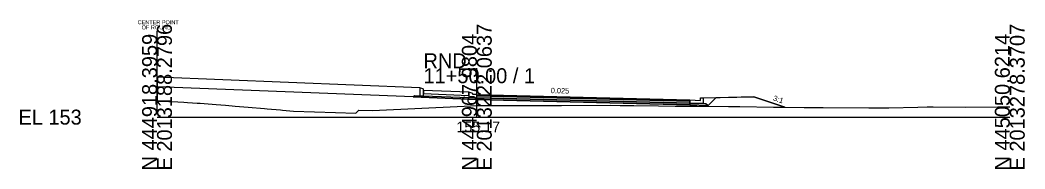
# Model space of a CAD drawing. Extents: x -26 to 163, y -10 to 7518.
# Drawn here: x -25.7 to 162.8, y 2990.3 to 3018.2 of the extents above; entities that cross this region are included whole.
import ezdxf

# ---------------------------------------------------------------- set-up
doc = ezdxf.new("R2010")
doc.units = 0
for name, color, linetype in [('Exist Cross Section Cell', 7, 'Continuous'), ('Exist XS Center Line Elevation Label', 7, 'Continuous'), ('Exist XS Ground Line', 7, 'Continuous'), ('Prop CMT Conc Surface', 7, 'Continuous'), ('Prop CMT Concrete Structures', 7, 'Continuous'), ('Prop CMT Pvmt Course 1', 7, 'Continuous'), ('Prop CMT Pvmt Course 1 CG', 7, 'Continuous'), ('Prop CMT Pvmt Course 2', 7, 'Continuous'), ('Prop CMT Pvmt Course 3', 7, 'Continuous'), ('Prop CMT Pvmt Surface', 7, 'Continuous'), ('Prop CMT Shear Line', 7, 'Continuous'), ('Prop CMT Shear Line Text', 7, 'Continuous'), ('Prop CMT Slope Grass', 7, 'Continuous'), ('Prop CMT Subgrade Earthwork', 7, 'Continuous'), ('Prop XS Earthwork Shape', 7, 'Continuous'), ('Prop XS SE Text', 7, 'Continuous'), ('Prop XS Side Slope Text', 7, 'Continuous')]:
    doc.layers.add(name, color=color, linetype=linetype)

msp = doc.modelspace()

# ---------------------------------------------------------------- linework, layer by layer
at = {"layer": 'Exist Cross Section Cell'}
for p, q in [((60, 3000), (60, 3009.16)), ((0, 3000), (60, 3000)), ((60, 3000), (160, 3000))]:
    msp.add_line(p, q, dxfattribs=at)
at = {"layer": 'Exist XS Ground Line'}
msp.add_lwpolyline([(0, 3003.05), (0.31, 3003.04), (2.2, 3002.95), (3.9, 3002.85), (5.06, 3002.79), (5.69, 3002.75), (6.63, 3002.69), (7.5, 3002.64), (8.08, 3002.6), (11.08, 3002.36), (12.87, 3002.22), (14.1, 3002.13), (14.67, 3002.08), (15.5, 3002.02), (17.12, 3001.89), (20.16, 3001.62), (20.65, 3001.58), (23.19, 3001.35), (23.53, 3001.32), (25.62, 3001.1), (33.49, 3000.87), (37.33, 3000.73), (37.84, 3001.3), (40.43, 3001.26), (57.62, 3002.07), (60, 3002.17), (60.93, 3002.21), (71.71, 3002.2), (73.03, 3002.2), (75.86, 3002.21), (85.13, 3002.22), (86.89, 3002.2), (89.47, 3002.17), (94.09, 3002.09), (97.23, 3002.07), (101.29, 3002.06), (107.23, 3002), (109.34, 3001.97), (115.68, 3001.84), (121.44, 3001.83), (124.99, 3001.79), (133.54, 3001.72), (137.28, 3001.73), (142.76, 3001.89), (144.47, 3001.91), (145.64, 3001.92), (151.67, 3001.86), (157.74, 3001.9), (158.87, 3001.9), (160, 3001.9)], dxfattribs=at)
at = {"layer": 'Prop CMT Conc Surface'}
for points in [[(50, 3005.18), (49.96, 3005.28), (49.85, 3005.33), (49.34, 3005.52)], [(50, 3005.02), (50, 3005.18)], [(60, 3004.22), (59.25, 3004.24), (59.25, 3004.41), (58.5, 3004.66)], [(101.98, 3003.09), (101.98, 3003.59), (102.48, 3003.59)], [(99.99, 3003.22), (101.98, 3003.09)]]:
    msp.add_lwpolyline(points, dxfattribs=at)
at = {"layer": 'Prop CMT Concrete Structures'}
for points in [[(50, 3005.18), (49.96, 3005.28), (49.85, 3005.33), (49.34, 3005.52)], [(49.34, 3005.52), (49.34, 3004.02)], [(49.34, 3004.02), (50, 3004.02)], [(50, 3005.02), (50, 3005.18)], [(50, 3004.02), (50, 3005.02)], [(50, 3005.02), (50, 3004.43)], [(58.5, 3004.66), (50, 3005)], [(50, 3004.41), (58.5, 3004.07)], [(60, 3004.22), (59.25, 3004.24), (59.25, 3004.41), (58.5, 3004.66)], [(58.5, 3004.66), (58.5, 3003.67)], [(58.5, 3004.07), (58.5, 3004.66)], [(58.5, 3003.67), (60, 3003.64)], [(60, 3003.64), (60, 3004.22)], [(99.99, 3003.22), (101.98, 3003.09), (101.98, 3003.59), (102.48, 3003.59)], [(102.48, 3003.59), (102.48, 3002.57), (99.99, 3002.63)], [(99.99, 3002.63), (99.99, 3003.22)]]:
    msp.add_lwpolyline(points, dxfattribs=at)
at = {"layer": 'Prop CMT Pvmt Course 1'}
for points in [[(60, 3004.22), (99.99, 3003.22)], [(60, 3003.97), (60, 3004.22)], [(99.99, 3002.97), (60, 3003.97)], [(99.99, 3003.22), (99.99, 3002.97)]]:
    msp.add_lwpolyline(points, dxfattribs=at)
msp.add_lwpolyline([(60, 3003.97), (60, 3004.09), (60, 3004.09), (60, 3003.97)], close=True, dxfattribs=at)
at = {"layer": 'Prop CMT Pvmt Course 1 CG'}
for points in [[(60, 3003.3), (60, 3003.64)], [(99.99, 3002.63), (102.98, 3002.56), (103.32, 3002.22)], [(99.99, 3002.3), (99.99, 3002.63)], [(103.4, 3002.21), (99.99, 3002.3)]]:
    msp.add_lwpolyline(points, dxfattribs=at)
at = {"layer": 'Prop CMT Pvmt Course 2'}
for points in [[(60, 3003.64), (60, 3003.97)], [(60, 3003.97), (99.99, 3002.97)], [(99.99, 3002.63), (60, 3003.64)], [(99.99, 3002.97), (99.99, 3002.63)]]:
    msp.add_lwpolyline(points, dxfattribs=at)
at = {"layer": 'Prop CMT Pvmt Course 3'}
for points in [[(50, 3004.02), (58.5, 3003.67)], [(60, 3003.64), (99.99, 3002.63)], [(60, 3003.3), (60, 3003.64)], [(99.99, 3002.3), (60, 3003.3)], [(99.99, 3002.63), (99.99, 3002.3)]]:
    msp.add_lwpolyline(points, dxfattribs=at)
at = {"layer": 'Prop CMT Pvmt Surface'}
msp.add_lwpolyline([(60, 3004.22), (99.99, 3003.22)], dxfattribs=at)
at = {"layer": 'Prop CMT Shear Line'}
msp.add_line((0, 3001.16), (0, 3016.16), dxfattribs=at)
at = {"layer": 'Prop CMT Slope Grass'}
for p, q in [((49.34, 3005.5), (0, 3007.47)), ((48.06, 3003.78), (0, 3005.7))]:
    msp.add_line(p, q, dxfattribs=at)
msp.add_lwpolyline([(102.48, 3003.59), (111.95, 3003.78), (117.77, 3001.84)], dxfattribs=at)
at = {"layer": 'Prop CMT Subgrade Earthwork'}
for p, q in [((0, 3007.47), (0, 3003.05)), ((48.34, 3004.06), (48.06, 3003.78))]:
    msp.add_line(p, q, dxfattribs=at)
for points in [[(48.06, 3003.78), (60, 3003.3)], [(48.34, 3004.06), (49.34, 3004.02)], [(99.99, 3002.3), (103.4, 3002.21), (104.82, 3003.63)], [(60, 3003.3), (99.99, 3002.3)]]:
    msp.add_lwpolyline(points, dxfattribs=at)
at = {"layer": 'Prop XS Earthwork Shape'}
msp.add_lwpolyline([(107.23, 3002), (109.34, 3001.97), (115.68, 3001.84), (117.77, 3001.84), (111.95, 3003.78), (104.82, 3003.63), (103.4, 3002.21), (99.99, 3002.3), (60, 3003.3), (48.06, 3003.78), (0, 3005.7), (0, 3003.05), (0.31, 3003.04), (2.2, 3002.95), (3.9, 3002.85), (5.06, 3002.79), (5.69, 3002.75), (6.63, 3002.69), (7.5, 3002.64), (8.08, 3002.6), (11.08, 3002.36), (12.87, 3002.22), (14.1, 3002.13), (14.67, 3002.08), (15.5, 3002.02), (17.12, 3001.89), (20.16, 3001.62), (20.65, 3001.58), (23.19, 3001.35), (23.53, 3001.32), (25.62, 3001.1), (33.49, 3000.87), (37.33, 3000.73), (37.84, 3001.3), (40.43, 3001.26), (57.62, 3002.07), (60, 3002.17), (60.93, 3002.21), (71.71, 3002.2), (73.03, 3002.2), (75.86, 3002.21), (85.13, 3002.22), (86.89, 3002.2), (89.47, 3002.17), (94.09, 3002.09), (97.23, 3002.07), (101.29, 3002.06)], close=True, dxfattribs=at)

# ---------------------------------------------------------------- texts
at = {"layer": 'Exist Cross Section Cell'}
for s, p in [('E 2013188.2796', (2.8, 2990)), ('E 2013222.0637', (62.8, 2990)), ('E 2013278.3707', (162.8, 2990)), ('N 444918.3959', (0, 2990)), ('N 444967.9804', (60, 2990)), ('N 445050.6214', (160, 2990))]:
    msp.add_text(s, height=2.8, rotation=90, dxfattribs=at).set_placement(p)
for s, p in [('RND', (50, 3009.16)), ('11+50.00 / 1', (50, 3006.36)), ('EL 153', (-26, 2998.6))]:
    msp.add_text(s, height=2.8, dxfattribs=at).set_placement(p)
at = {"layer": 'Exist XS Center Line Elevation Label'}
msp.add_text('155.17', height=2, dxfattribs=at).set_placement((56.18, 2997.17))
at = {"layer": 'Prop CMT Shear Line Text'}
for s, p in [('CENTER POINT', (-3.64, 3017.41)), ('OF ROUND', (-2.88, 3016.44))]:
    msp.add_text(s, height=0.75, dxfattribs=at).set_placement(p)
at = {"layer": 'Prop XS SE Text'}
msp.add_text('0.025', height=1, rotation=358.5613, dxfattribs=at).set_placement((73.87, 3004.5))
at = {"layer": 'Prop XS Side Slope Text'}
msp.add_text('3:1', height=1, rotation=341.5651, dxfattribs=at).set_placement((115.52, 3003.16))

doc.saveas('drawing.dxf')
